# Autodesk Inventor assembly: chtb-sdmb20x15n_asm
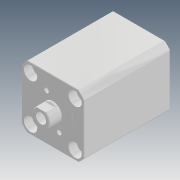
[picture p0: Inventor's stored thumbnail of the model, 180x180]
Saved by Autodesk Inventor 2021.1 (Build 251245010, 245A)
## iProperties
Company: Microsoft
Created: 2018-05
Part Number: chtb-sdmb20x15n_asm
Description: STEP AP214
Document SubType Name: Assembly
Designer: user
Title: chtb-sdmb20x15n_asm.STEP
Author: Windows
Revision Number: ÈÎºÎ
Sending System: SolidWorks 2015
Preprocessor: SwSTEP 2.0
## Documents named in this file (4)
- D:\Vault_2016\Projekty\Clamptek\Hydraulic\CHTB\CHTB-20\Inventor\CHTB-SDMB20x15N\chtb-sdmb20x15n_asm.iam
- D:\Vault_2016\Projekty\Clamptek\Hydraulic\CHTB\CHTB-20\Inventor\CHTB-SDMB20x15N\CHTB-SDMB20X15NBT.ipt
- D:\Vault_2016\Projekty\Clamptek\Hydraulic\CHTB\CHTB-20\Inventor\CHTB-SDMB20x15N\CHTB-SDMB20X15NHSG.ipt
- D:\Vault_2016\Projekty\Clamptek\Hydraulic\CHTB\CHTB-20\Inventor\CHTB-SDMB20x15N\QG_3.ipt
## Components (3 placed, 3 different names)
1. CHTB-SDMB20X15NBT_1
2. CHTB-SDMB20X15NHSG_2
3. QG_3_3
